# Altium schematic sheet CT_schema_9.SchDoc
size 277 x 170 mm
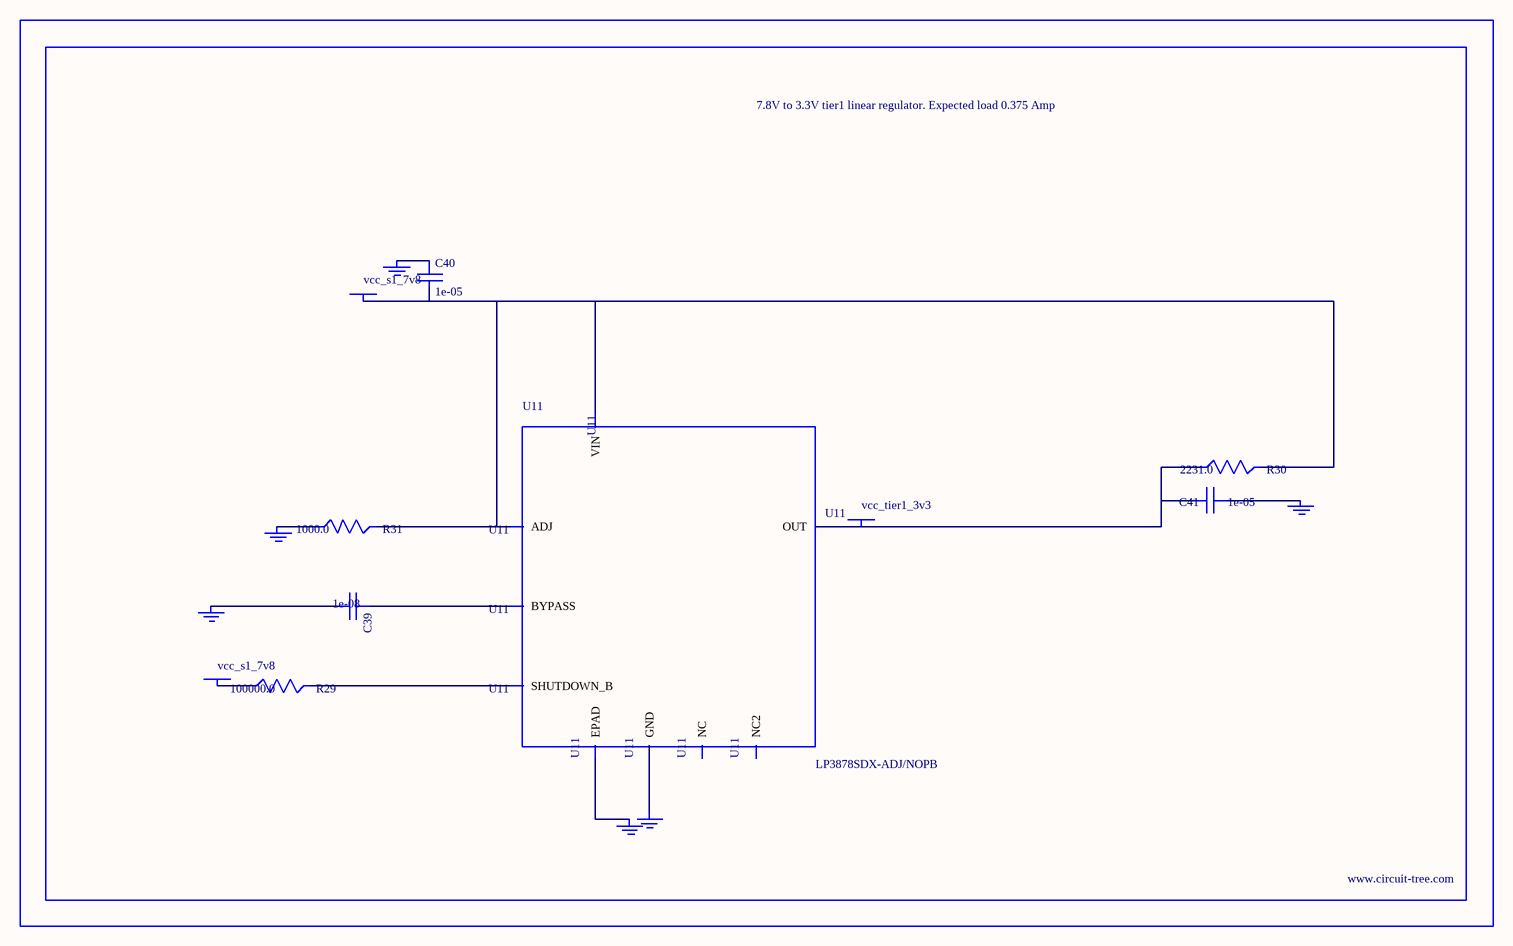
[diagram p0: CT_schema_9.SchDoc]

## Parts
BORDER8  (no value)
C39  1e-08  [C0402]
C40  1e-05  [C1206]
C41  1e-05  [C1210]
GND_INSTANCE_8_0  (no value)
GND_INSTANCE_8_1  (no value)
GND_INSTANCE_8_2  (no value)
GND_INSTANCE_8_3  (no value)
GND_INSTANCE_8_4  (no value)
GND_INSTANCE_8_5  (no value)
POWER_INSTANCE_8_0  vcc_s1_7v8
POWER_INSTANCE_8_1  vcc_s1_7v8
POWER_INSTANCE_8_2  vcc_tier1_3v3
R29  100000.0  [R0603]
R30  2231.0  [R0603]
R31  1000.0  [R0603]
U11  LP3878SDX-ADJ/NOPB  [WSON-8]

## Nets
NetC39_1: C39.1 U11.1(BYPASS)
NetC39_2: C39.2 GND_INSTANCE_8_0.0(GND)
NetC40_1: C40.1 GND_INSTANCE_8_1.0(GND)
NetC40_2: C40.2 POWER_INSTANCE_8_0.0(PWR) R30.2 R31.2 U11.4(VIN) U11.6(ADJ)
NetC41_1: C41.1 GND_INSTANCE_8_2.0(GND)
NetC41_2: C41.2 POWER_INSTANCE_8_2.0(PWR) R30.1 U11.5(OUT)
NetGND_INSTANCE_8_3_0: GND_INSTANCE_8_3.0(GND) R31.1
NetGND_INSTANCE_8_4_0: GND_INSTANCE_8_4.0(GND) U11.PAD(EPAD)
NetGND_INSTANCE_8_5_0: GND_INSTANCE_8_5.0(GND) U11.3(GND)
NetPOWER_INSTANCE_8_1_0: POWER_INSTANCE_8_1.0(PWR) R29.1
NetR29_2: R29.2 U11.8(SHUTDOWN_B)

Not connected (* = marked no-connect by the designer): U11 2(NC) 7(NC2)

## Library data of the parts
BORDER8 = BORDER_PAGE8
C39 = C0402C103K3RAC
C40 = C1206C106K3RACTU
C41 = GRM32DR61E106MA12L
GND_INSTANCE_8_0-GND_INSTANCE_8_5 = GND
POWER_INSTANCE_8_0-POWER_INSTANCE_8_2 = PWR
R29 = RC0603JR-07100KL
R30 = R30
R31 = RC0603JR-071KL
